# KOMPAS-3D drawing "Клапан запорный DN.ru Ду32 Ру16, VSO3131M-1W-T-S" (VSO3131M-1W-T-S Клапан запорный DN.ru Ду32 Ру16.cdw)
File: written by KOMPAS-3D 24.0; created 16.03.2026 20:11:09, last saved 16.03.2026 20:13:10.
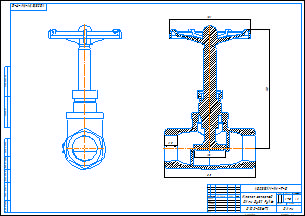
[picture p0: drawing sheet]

Document properties: c3d_UniqueCompID: 94d3474e-3e6e-4ddd-ad0b-ef51eb5e31da; Обозначение: VSO3131M-1W-T-S; Наименование: Клапан запорный DN.ru Ду32 Ру16; Материал: Сталь 10 ГОСТ 1050-2013; Автор: artiomk228874@gmail.com; Класс точности: c; Знак неуказанной шероховатости: Шероховатость не задана; Рассекать на разрезах: Да; Автор: artiomk228874@gmail.com; Форматы листов документа: A2; Полное имя файла: VSO3131M-1W-T-S Клапан запорный DN.ru Ду32 Ру16.m3d; Масса: 0.76; Наименование: Клапан запорный DN.ru Ду32 Ру16; Количество листов документа: 1; Примечание: D100-03672

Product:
- Body: Тело 1  | qty 1
    Масса: 0.617629
- Part/product: Клапан запорный DN.ru Ду32 Ру16  | designation VSO3131M-1W-T-S
    Масса: 0.76
    Раздел спецификации: Прочие изделия
    Форматы листов документа: A2
    Примечание: D100-03672
    additional columns: 94d3474e-3e6e-4ddd-ad0b-ef51eb5e31da; VSO3131M-1W-T-S; Сталь 10 ГОСТ 1050-2013; artiomk228874@gmail.com; c; Шероховатость не задана; Да

Views: Проекционный вид 2
Referenced files in C:\Users\artio\OneDrive\Рабочий стол\Клапан запорный DN.ru VSO3131M-1W-T-S Ду15-Ду50 Ру16\Ду32\: VSO3131M-1W-T-S Клапан запорный DN.ru Ду32 Ру16.m3d, VSO3131M-1W-T-S Клапан запорный DN.ru Ду32 Ру16.cdw
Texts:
  VSO3131M-1W-T-S
  Клапан запорный
  DN.ru Ду32 Ру16
  Клапан запорный DN.ru Ду32 Ру16
  VSO3131M-1W-T-S Клапан запорный DN.ru Ду32 Ру16
Dimensions and other numbers on the sheet: 0; 3; 4; 2:1; 1; 2; 0,76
